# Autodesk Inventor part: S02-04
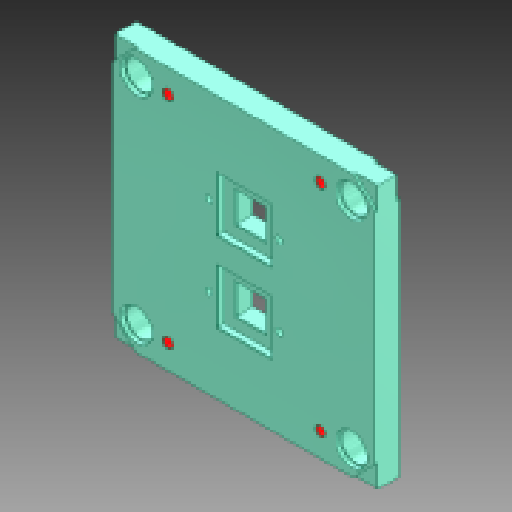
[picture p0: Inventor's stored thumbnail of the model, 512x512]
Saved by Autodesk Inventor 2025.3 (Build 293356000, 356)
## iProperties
Created: 2025-04
Part Number: S02-04
Material: Všeobecné
Document SubType Name: Modeling
Designer: Patrik
Density: 1 g/cm^3
Appearance: Výchozí
Description: Deska tvarová pravá
Stock Number: F 50 /396 396/ 36/1730
Mass: 5154.11 g
Surface Area: 3951.78 cm^2
Volume: 5154.11 cm^3
User Status: 1730
Author: Patrik
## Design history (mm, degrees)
feature "Base1"
feature "Vyřezání1"
sketch "Náčrt2"
  geometry: L1 (123.5, 93.526)-(123.5, 174.526) reference; L2 (204.5, 93.526)-(123.5, 93.526) reference; L3 (204.5, 174.526)-(204.5, 93.526) reference; L4 (123.5, 174.526)-(204.5, 174.526) reference; L5 (141.5, 111.526)-(141.5, 156.526) reference; L6 (141.5, 156.526)-(186.5, 156.526) reference; L7 (186.5, 156.526)-(186.5, 111.526) reference; L8 (186.5, 111.526)-(141.5, 111.526) reference; L9 (123.5, 213.526)-(123.5, 294.526) reference; L10 (204.5, 213.526)-(123.5, 213.526) reference; L11 (204.5, 294.526)-(204.5, 213.526) reference; L12 (123.5, 294.526)-(204.5, 294.526) reference; L13 (141.5, 231.526)-(141.5, 276.526) reference; L14 (141.5, 276.526)-(186.5, 276.526) reference; L15 (186.5, 276.526)-(186.5, 231.526) reference; L16 (186.5, 231.526)-(141.5, 231.526) reference; 1 further point
extrude "Vysunutí2" cut sketch "Náčrt2" stored distance "d2" = 10; taper "d3" = 0 deg
chamfer "Zkosení1" distance "d4" = 1; stored, may be unused: second distance "d5" = 2, angle "d6" = 45 deg
feature "Vyřezání2"
sketch "Náčrt3"
  geometry: C1 r 2.455 at (0, 0) reference; C2 r 2.455 at (0, -120) reference; C3 r 3 at (0, 0) reference; C4 r 3 at (0, -120) reference; 1 further point
extrude "Vysunutí3" cut sketch "Náčrt3" stored distance "d7" = 10; taper "d8" = 0 deg
sketch "Náčrt4"
  geometry: C1 r 5 at (0, 0) reference; C2 r 5 at (0, 120); 1 further point
  constraints: 1 centre point
extrude "Vysunutí4" cut sketch "Náčrt4" stored distance "d9" = 10; taper "d10" = 0 deg
mirror "Zrcadlit1"
feature "Vyřezání3"
sketch "Náčrt5"
  geometry: C1 r 3.5 at (243.575, 254.026) reference; C2 r 3.5 at (243.575, 134.026) reference; C3 r 3.5 at (152.425, 254.026) reference; C4 r 3.5 at (152.425, 134.026) reference; 1 further point
extrude "Vysunutí5" cut sketch "Náčrt5" stored distance "d11" = 10; taper "d12" = 0 deg
chamfer "Zkosení2" distance "d13" = 0.535; stored, may be unused: second distance "d14" = 2, angle "d15" = 45 deg
node "Těleso1"
node "Promítnutá smyčka2"
node "Promítnutá smyčka3"
feature "Plocha4"
node "Povrch4"
feature "Plocha5"
node "Povrch5"
feature "Plocha6"
node "Povrch6"
